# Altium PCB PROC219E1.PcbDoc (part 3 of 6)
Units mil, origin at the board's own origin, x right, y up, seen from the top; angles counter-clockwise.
Board outline 5354.33 x 5354.33 mil, 4 copper layers (Top Layer, Inner Layer 1, Inner Layer 2, Bottom Layer), stack 62.449 mil thick; 579 components, 299 nets, 1709 pads, 802 vias.
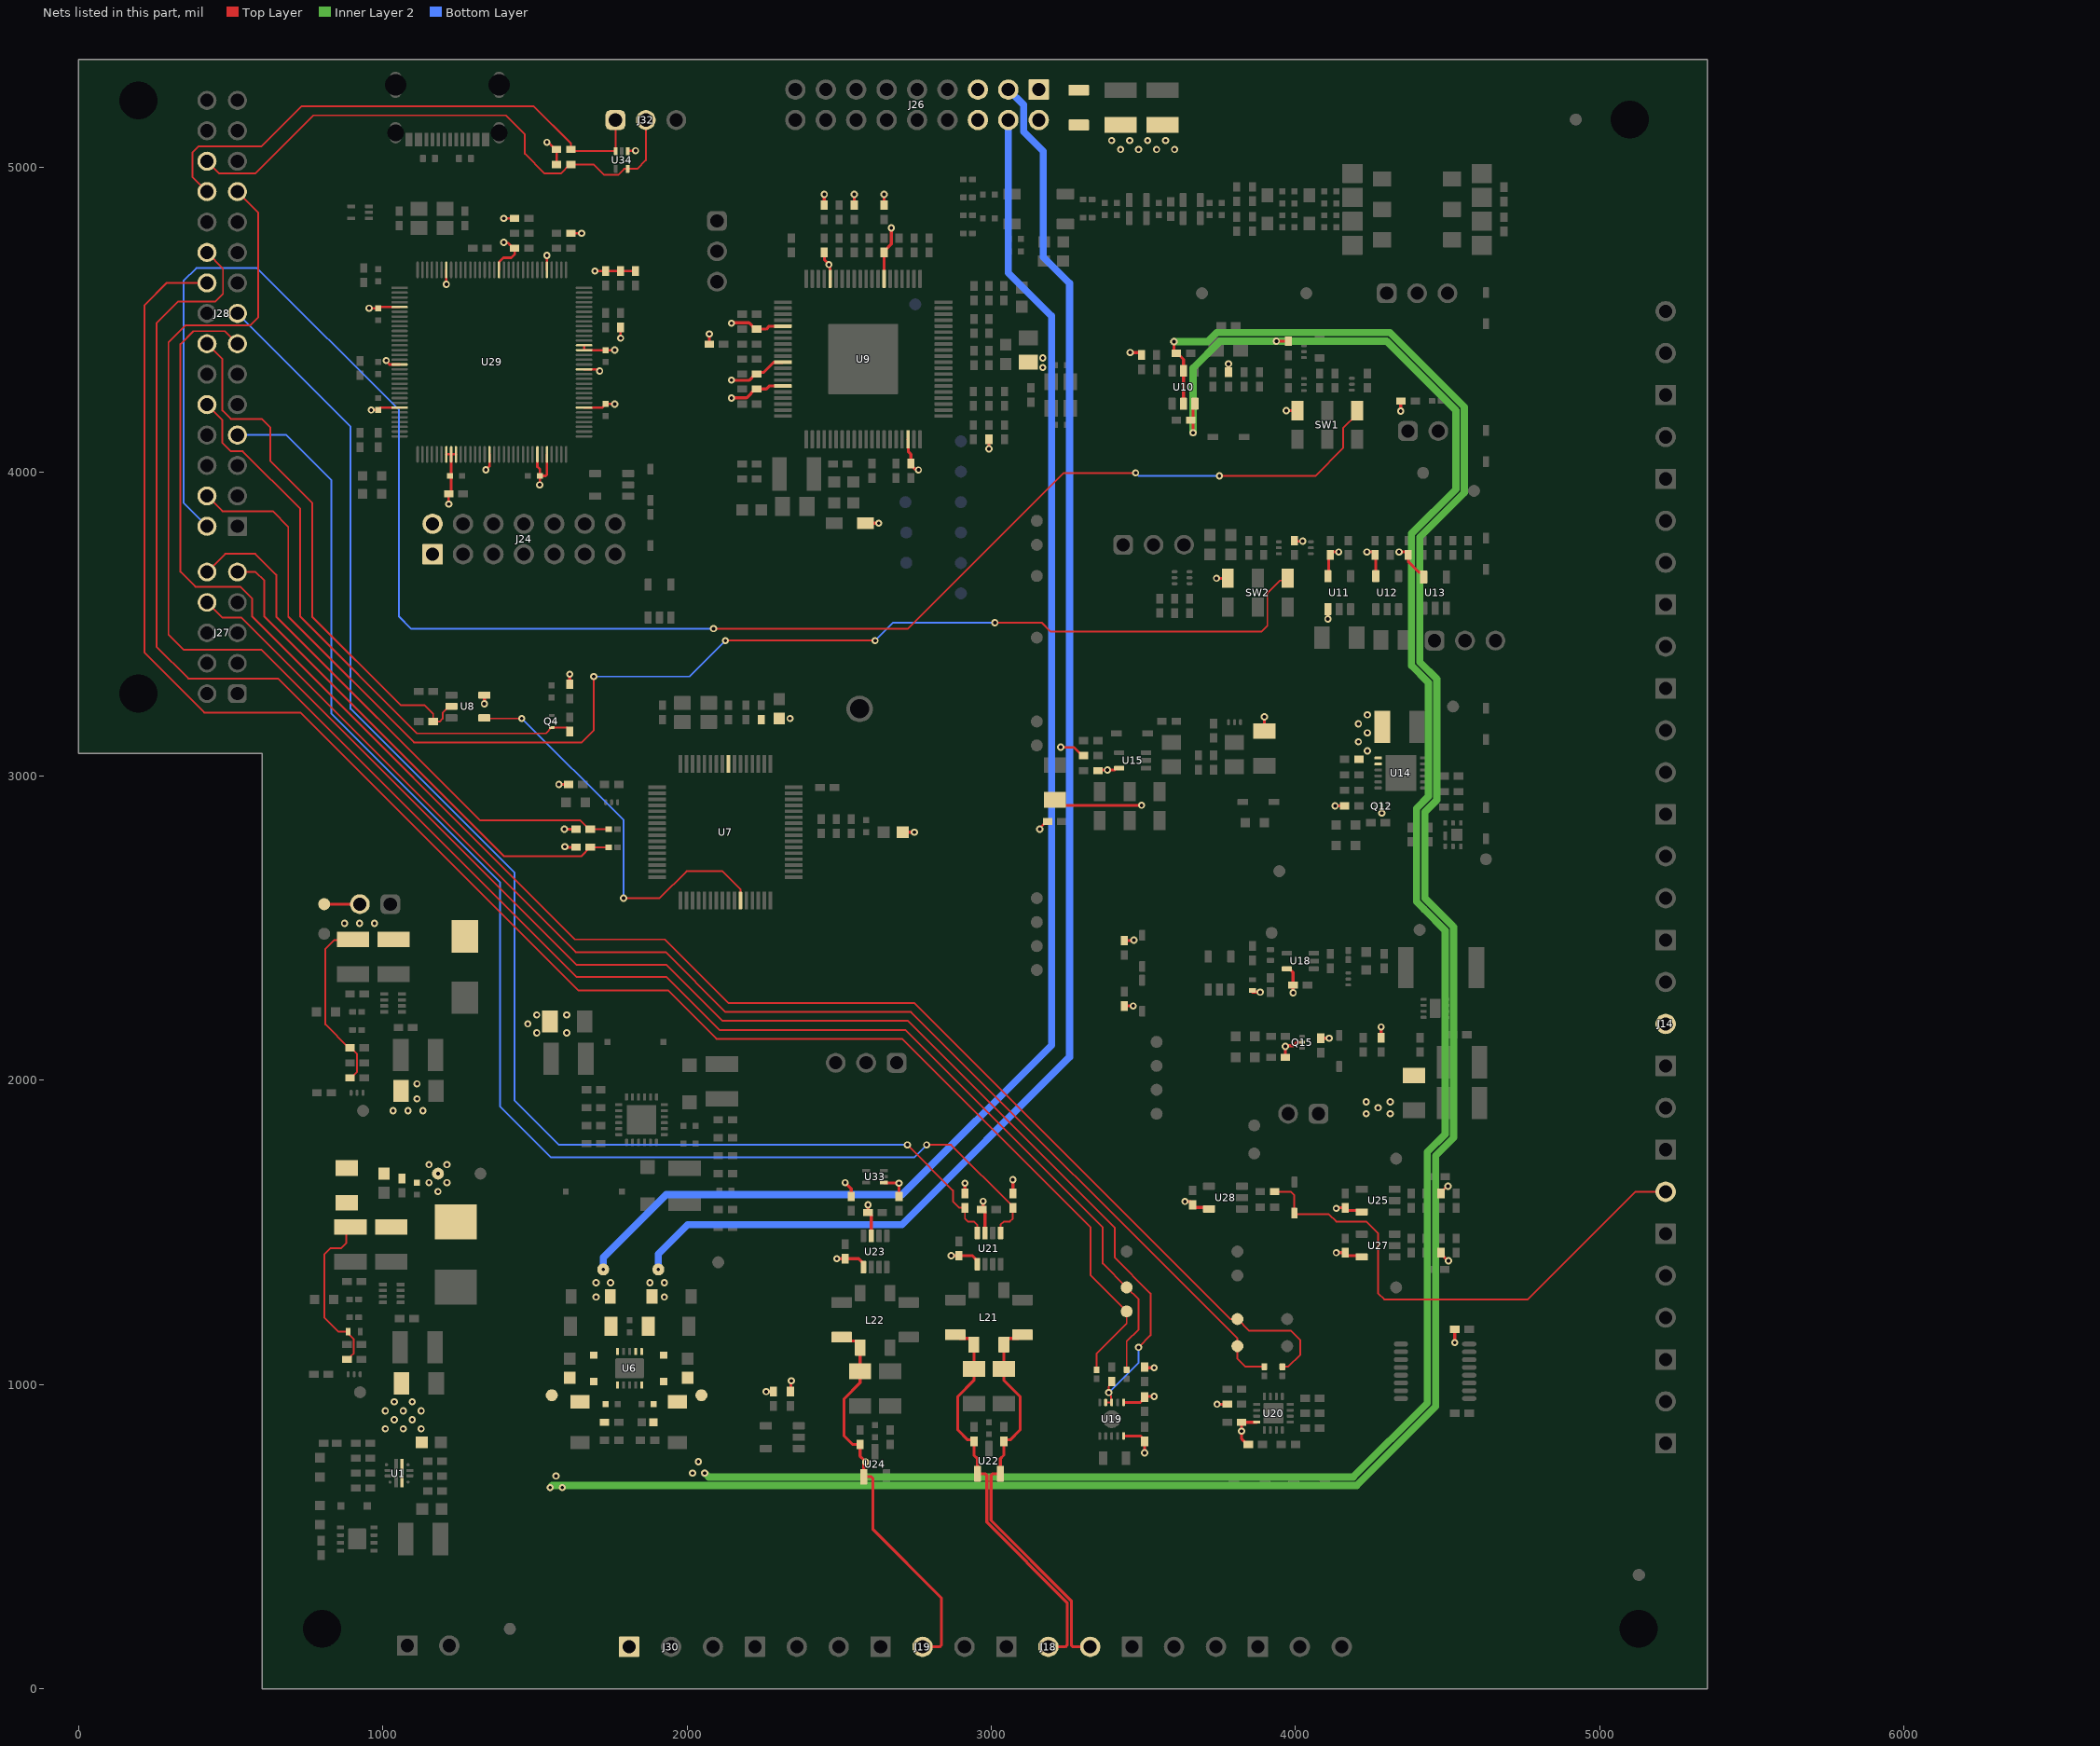
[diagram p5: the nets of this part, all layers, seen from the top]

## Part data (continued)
L13: library part CMP-0100963-1, "WE-PMCI SMT Power Molded Chip Inductor, size 1210, 2.2uH, 4.5A, 75mOhm", DC Resistance=70mOhm, DC Resistance Max=75mOhm, Manufacturer="Wurth Elektronik", Operating Temperature Max=125°C, Operating Temperature Min=-40°C, Rated Current=4.5A, Saturation Current=4.8A, Self Resonant Frequency=35MHz
L15 L16 L19 L20: library part CMP-0124834-1, "Wire Wound RF Inductor 270nH ±2% 260mA 2.42Ω 0603 (1608)", Manufacturer=Murata, Operating Temperature Range="-55°C to +125°C", Self Resonant Frequency=1.25GHz, Test Frequency=100MHz, Tolerance_%=2%
L17 L18: library part CMP-0124833-1, "Multilayer Type Inductor for Power Lines, 0805 (2012), 4.7μH, 20%, 0.288Ω, 0.8A", Manufacturer=Murata, Operating Temperature Range="-55℃ to +125℃", Self Resonant Frequency=30MHz, Test Frequency=1MHz, Tolerance_%=20%
L21 L22: library part CMP-0084086-1, "100µH @ 100kHz 2 Line Common Mode Choke Surface Mount 5.8 kOhms @ 10MHz 150mA DCR 2Ohm", Digikey Part Number=445-3959-1-ND, Impedance At Frequency="5800Ω @ 10MHz", Manufacturer=TDK, Mouser Part Number=810-ACT45B1012PTL003, Operating Temperature Range="-40°C to +150°C", Test Frequency=100kHz, Tolerance_%=+50/-30%
Logo1: library part CMP-0074844-1
Logo2 Logo6: library part CMP-0074838-1, "Texas Instrument Corporate Signature"
Logo3: library part CMP-0074840-1, "ESD Susceptible Symbol"
Logo4: library part CMP-0074847-1, "FCC_disclaimer"
Logo5: library part CMP-0074769-4, Manufacturer="Texas Instruments"
MH1 MH2 MH3 MH4 MH5: library part CMP-0078424-2, "PCB Mounting Hole, No Pad", Manufacturer=Any, PartNumber=N/A
NT1: library part CMP-0078142-6, "Single point connection between nets.", Manufacturer=N/A
Q1 Q2 Q3 Q4 Q6 Q7 Q9 Q10 Q11 Q14 Q16: library part CMP-0067551-1, "MOSFET, N-CH, 30 V, 5.9 A, YJK0003A (PICOSTAR-3)", Alternate Manufacturer=None, Manufacturer="Texas Instruments", Supplier Part Number 1=296-45068-1-ND, Value1="0.033 ohm", Value2="1.9 nC"
Q5 Q8 Q12 Q15: library part CMP-0000031-3, "MOSFET, P-CH, -20 V, -5.3 A, YJK0003A (PICOSTAR-3)", Alternate Manufacturer=None, Manufacturer="Texas Instruments", Value2="2.7 nC"
Q13: library part CMP-0000585-1, "MOSFET, N-CH, 30 V, 22 A, DQK0006C (WSON-6)", Alternate Manufacturer=None, Manufacturer="Texas Instruments", Supplier Part Number 1=296-37193-1-ND, Value1=0.02, Value2="2.4 nC"
R1 R7 R13 R19 R42 R43 R44 R45 R47 R48 R49 R50 R96 R123 R127 R134 R135 R140 R141 R148 R167 R168 R169 R170: library part CMP-0026700-1, "RES, 4.70 k, 1%, 0.1 W, 0402", Manufacturer=Panasonic, Power_W=100mW, Supplier Part Number 1=P4.70KLCT-ND, TempCo="100 ppm/C", Tolerance_%=1%, Value2=0.1W, Value_Code=4k70, ValueDisplayed=4.70k
R2: library part CMP-0026393-2, "RES, 475 k, 1%, 0.063 W, AEC-Q200 Grade 0, 0402", Manufacturer=Vishay-Dale, Power_W=63mW, Supplier Part Number 1=541-475KLCT-ND, TempCo="100 ppm/C", Tolerance_%=1%, Value2=0.063W, Value_Code=475k
R3 R133 R138 R139 R144: library part CMP-0094724-1, "Jumper 0.25W, 1/4W Chip Resistor 1206 (3216 Metric) - Thick Film", Digikey Part Number=541-4170-1-ND, Manufacturer=Vishay, Mouser Part Number=71-CRCW12060000Z0EAC, Operating Temperature Range="-55°C to +155°C", Power_W=250mW
R4: library part CMP-0025975-3, "RES, 11.0 k, 1%, 0.063 W, AEC-Q200 Grade 0, 0402", Manufacturer=Vishay-Dale, Power_W=63mW, Supplier Part Number 1=541-11.0KLCT-ND, TempCo="100 ppm/C", Tolerance_%=1%, Value2=0.063W, Value_Code=11k0, ValueDisplayed=11.0k
R5: library part CMP-0026542-2, "RES, 750, 1%, 0.063 W, AEC-Q200 Grade 0, 0402", Manufacturer=Vishay-Dale, Power_W=63mW, Supplier Part Number 1=541-750LCT-ND, TempCo="100 ppm/C", Tolerance_%=1%, Value2=0.063W, Value_Code=750R, ValueDisplayed=750
R6 R37: library part CMP-0026737-1, "RES, 47.0 k, 1%, 0.0625 W, 0402", Manufacturer="Yageo America", Power_W=62.5mW, Supplier Part Number 1=311-47.0KLRCT-ND, TempCo="100 ppm/C", Tolerance_%=1%, Value2=0.0625W, Value_Code=47k0, ValueDisplayed=47.0k
R8 R11 R14 R17 R33 R34 R51 R52 R53 R54 R55 R56 R67 R118 R125 R126 R128 R131: library part CMP-0095664-1, "Jumper 0.063W, 1/16W Chip Resistor 0402 (1005 Metric) - Thick Film", Digikey Part Number=A106025CT-ND, Manufacturer="TE Connectivity", Mouser Part Number=279-CRG0402ZR, Operating Temperature Range="-55°C to +155°C", Power_W=62.5mW, TempCo=200ppm/°C
R9 R12 R15 R18 R23 R27 R29 R31 R32 R36 R38 R39 R40 R70 R71 R72 R75 R76 R78 R82 R85 R86 R87 R88 R90 R91 R92 R93 R95 R99 R101 R103 R110 R111 R112 R129 R130 R132 R145 R146 R147 R149 R150 R151 R161 R162: library part CMP-0026658-1, "RES, 10.0 k, 1%, 0.1 W, 0402", Manufacturer=Panasonic, Power_W=100mW, Supplier Part Number 1=P10.0KLCT-ND, TempCo="100 ppm/C", Tolerance_%=1%, Value2=0.1W, Value_Code=10k0, ValueDisplayed=10.0k
R10: library part CMP-0026539-2, "RES, 73.2 k, 1%, 0.063 W, AEC-Q200 Grade 0, 0402", Manufacturer=Vishay-Dale, Power_W=63mW, Supplier Part Number 1=541-73.2KLCT-ND, TempCo="100 ppm/C", Tolerance_%=1%, Value2=0.063W, Value_Code=73k2, ValueDisplayed=73.2k
R16: library part CMP-0077552-1, "RES, 45.3 k, 1%, 0.063 W, 0402", Manufacturer="Yageo America", Power_W=63mW, Supplier Part Number 1=311-45.3KLRCT-ND, TempCo="100 ppm/C", Tolerance_%=1%, Value2=0.063W, Value_Code=45k3, ValueDisplayed=45.3k
R20: library part CMP-0123016-1, "Res Thick Film 0402 91K Ohm 1% 0.063W(1/16W) ±100ppm/C Pad SMD T/R", Digikey Part Number=13-RC0402FR-1391KLCT-ND, Manufacturer=YAGEO, Mouser Part Number=603-RC0402FR-1391KL, Operating Temperature Range="-55°C to +155°C", Power_W=63mW, TempCo=100ppm/°C, Tolerance_%=1%
R21: library part CMP-0026615-3, "RES, 976 k, 1%, 0.063 W, AEC-Q200 Grade 0, 0402", Manufacturer=Vishay-Dale, Power_W=63mW, Supplier Part Number 1=541-976KLCT-ND, TempCo="100 ppm/C", Tolerance_%=1%, Value2=0.063W, Value_Code=976k
R22: library part CMP-0026609-3, "RES, 93.1 k, 1%, 0.063 W, AEC-Q200 Grade 0, 0402", Manufacturer=Vishay-Dale, Power_W=63mW, Supplier Part Number 1=541-93.1KLCT-ND, TempCo="100 ppm/C", Tolerance_%=1%, Value2=0.063W, Value_Code=93k1, ValueDisplayed=93.1k
R24: library part CMP-0120089-1, "68 kOhms ±1% 0.063W, 1/16W Chip Resistor 0402 (1005 Metric) Thick Film", Digikey Part Number=1292-WR04X6802FTLCT-ND, Manufacturer="Walsin Technology", Mouser Part Number=791-WR04X6802FTL, Operating Temperature Range="-55°C to +155°C", Power_W=63mW, TempCo=100ppm/°C, Tolerance_%=1%
R25: library part CMP-0026549-2, "RES, 787 k, 1%, 0.063 W, AEC-Q200 Grade 0, 0402", Manufacturer=Vishay-Dale, Power_W=63mW, Supplier Part Number 1=541-787KLCT-ND, TempCo="100 ppm/C", Tolerance_%=1%, Value2=0.063W, Value_Code=787k
R26 R58 R158: library part CMP-0026656-1, "RES, 100, 1%, 0.1 W, 0402", Manufacturer=Panasonic, Power_W=100mW, Supplier Part Number 1=P100LCT-ND, TempCo="100 ppm/C", Tolerance_%=1%, Value2=0.1W, Value_Code=100R, ValueDisplayed=100
R28 R30 R84 R102: library part CMP-0026721-1, "RES, 100 k, 1%, 0.0625 W, 0402", Manufacturer="Yageo America", Power_W=62.5mW, Supplier Part Number 1=311-100KLRCT-ND, TempCo="100 ppm/C", Tolerance_%=1%, Value2=0.0625W, Value_Code=100k
R35 R94 R107 R109 R120: library part CMP-0026878-3, "RES, 220, 5%, 0.063 W, AEC-Q200 Grade 0, 0402", Manufacturer=Vishay-Dale, Power_W=63mW, Supplier Part Number 1=541-220JCT-ND, TempCo="200 ppm/C", Tolerance_%=5%, Value2=0.063W, Value_Code=220R, ValueDisplayed=220
R41 R46: library part CMP-0022751-4, "RES, 10.0, 1%, 0.1 W, 0603", Manufacturer=Yageo, Power_W=100mW, Supplier Part Number 1=311-10.0HRCT-ND, TempCo="100 ppm/C", Tolerance_%=1%, Value2=0.1W, Value_Code=10R0, ValueDisplayed=10.0
R57 R77 R119: library part CMP-0026727-1, "RES, 1.00 M, 1%, 0.063 W, 0402", Manufacturer="Yageo America", Power_W=63mW, Supplier Part Number 1=311-1.00MLRCT-ND, TempCo="100 ppm/C", Tolerance_%=1%, Value2=0.063W, Value_Code=1M00, ValueDisplayed=1.00M
R59: library part CMP-0026468-2, "RES, 5.76 k, 1%, 0.063 W, AEC-Q200 Grade 0, 0402", Manufacturer=Vishay-Dale, Power_W=63mW, Supplier Part Number 1=541-5.76KLCT-ND, TempCo="100 ppm/C", Tolerance_%=1%, Value2=0.063W, Value_Code=5k76, ValueDisplayed=5.76k
R60 R62 R63: library part CMP-0026677-1, "RES, 200 k, 1%, 0.1 W, 0402", Manufacturer=Panasonic, Power_W=100mW, Supplier Part Number 1=P200KLCT-ND, TempCo="100 ppm/C", Tolerance_%=1%, Value2=0.1W, Value_Code=200k
R61: library part CMP-0019089-2, "RES, 1.00 k, 0.1%, 0.25 W, 0805", Manufacturer="TE Connectivity", Power_W=250mW, Supplier Part Number 1=A110543CT-ND, TempCo="25 ppm/C", Tolerance_%=0.1%, Value2=0.25W, Value_Code=1k00, ValueDisplayed=1.00k
R64 R106: library part CMP-0026449-2, "RES, 54.9 k, 1%, 0.063 W, AEC-Q200 Grade 0, 0402", Manufacturer=Vishay-Dale, Power_W=63mW, Supplier Part Number 1=541-54.9KLCT-ND, TempCo="100 ppm/C", Tolerance_%=1%, Value2=0.063W, Value_Code=54k9, ValueDisplayed=54.9k
R65: library part CMP-0026494-2, "RES, 63.4 k, 1%, 0.063 W, AEC-Q200 Grade 0, 0402", Manufacturer=Vishay-Dale, Power_W=63mW, Supplier Part Number 1=541-63.4KLCT-ND, TempCo="100 ppm/C", Tolerance_%=1%, Value2=0.063W, Value_Code=63k4, ValueDisplayed=63.4k
R66 R83 R108 R117 R154 R155 R156 R157: library part CMP-0026725-1, "RES, 1.00 k, 1%, 0.0625 W, 0402", Manufacturer="Yageo America", Power_W=62.5mW, Supplier Part Number 1=311-1.00KLRCT-ND, TempCo="100 ppm/C", Tolerance_%=1%, Value2=0.0625W, Value_Code=1k00, ValueDisplayed=1.00k
R68: library part CMP-0026241-2, "RES, 2.74 k, 1%, 0.063 W, AEC-Q200 Grade 0, 0402", Manufacturer=Vishay-Dale, Power_W=63mW, Supplier Part Number 1=541-2.74KLCT-ND, TempCo="100 ppm/C", Tolerance_%=1%, Value2=0.063W, Value_Code=2k74, ValueDisplayed=2.74k
R69: library part CMP-0026082-3, "RES, 1.30 k, 1%, 0.063 W, AEC-Q200 Grade 0, 0402", Manufacturer=Vishay-Dale, Power_W=63mW, Supplier Part Number 1=541-1.30KLCT-ND, TempCo="100 ppm/C", Tolerance_%=1%, Value2=0.063W, Value_Code=1k30, ValueDisplayed=1.30k
R73 R97 R104: library part CMP-0018797-2, "RES, 1.00 k, 0.1%, 0.25 W, 1206", Manufacturer="TE Connectivity", Power_W=250mW, Supplier Part Number 1=A105676-ND, TempCo="15 ppm/C", Tolerance_%=0.1%, Value2=0.25W, Value_Code=1k00, ValueDisplayed=1.00k
R74: library part CMP-0019464-2, "RES, 10.0 k, 0.1%, 0.125 W, 0805", Manufacturer="Yageo America", Power_W=125mW, Supplier Part Number 1=603-RT0805BRD0710KL, TempCo="25 ppm/C", Tolerance_%=0.1%, Value2=0.125W, Value_Code=10k0, ValueDisplayed=10.0k
R79 R100: library part CMP-0026919-5, "RES, 3.6 k, 5%, 0.063 W, AEC-Q200 Grade 0, 0402", Manufacturer=Vishay-Dale, Power_W=63mW, Supplier Part Number 1=541-3.6KJCT-ND, TempCo="200 ppm/C", Tolerance_%=5%, Value2=0.063W, Value_Code=3k60, ValueDisplayed=3.6k
R80: library part CMP-0024081-3, "RES, 2.74 k, 0.1%, 0.1 W, 0603", Manufacturer="Yageo America", Power_W=100mW, TempCo="25 ppm/C", Tolerance_%=0.1%, Value2=0.1W, Value_Code=2k74, ValueDisplayed=2.74k
R81: library part CMP-0023888-3, "RES, 1.30 k, 0.1%, 0.1 W, 0603", Manufacturer="Yageo America", Power_W=100mW, TempCo="25 ppm/C", Tolerance_%=0.1%, Value2=0.1W, Value_Code=1k30, ValueDisplayed=1.30k
R89: library part CMP-0026017-3, "RES, 14.7 k, 1%, 0.063 W, AEC-Q200 Grade 0, 0402", Manufacturer=Vishay-Dale, Power_W=63mW, Supplier Part Number 1=541-14.7KLCT-ND, TempCo="100 ppm/C", Tolerance_%=1%, Value2=0.063W, Value_Code=14k7, ValueDisplayed=14.7k
R98 R105: library part CMP-0019763-2, "RES, 200, 0.1%, 0.125 W, 0805", Manufacturer="Yageo America", Power_W=125mW, TempCo="25 ppm/C", Tolerance_%=0.1%, Value2=0.125W, Value_Code=200R, ValueDisplayed=200
R113 R115: library part CMP-0001694-1, "150 Ohms ±0.1% 0.063W, 1/16W Chip Resistor 0402 (1005 Metric) Anti-Sulfur, Automotive AEC-Q200, Moisture Resistant Thin Film", Digikey Part Number=541-2077-1-ND, Manufacturer="Vishay Dale", Mouser Part Number=71-TNPW0402150RBEED, Operating Temperature Range="-55°C to +155°C", Power_W=100mW, TempCo=25ppm/°C, Tolerance_%=0.1%
R114: library part CMP-0026201-2, "RES, 25.5 k, 1%, 0.063 W, AEC-Q200 Grade 0, 0402", Manufacturer=Vishay-Dale, Power_W=63mW, Supplier Part Number 1=541-25.5KLCT-ND, TempCo="100 ppm/C", Tolerance_%=1%, Value2=0.063W, Value_Code=25k5, ValueDisplayed=25.5k
R116: library part CMP-0015788-2, "RES, 0.5, 1%, 2 W, 2512", Manufacturer="Stackpole Electronics Inc", Power_W=2W, Supplier Part Number 1=CSRN2512FKR500CT-ND, TempCo="200 ppm/C", Tolerance_%=1%, Value_Code=R500, ValueDisplayed=0.5
R121 R122 R152: library part CMP-0065360-1, "RES, 10.0 k, .1%, .0625 W, 0402", Manufacturer="Yageo America", Power_W=62.5mW, Supplier Part Number 1=YAG1346CT-ND, TempCo="25 ppm/C", Tolerance_%=0.1%, Value1=.1%, Value2=.0625W, Value_Code=10k0, ValueDisplayed=10.0k
R124: library part CMP-0126832-1, "Res Thick Film 0805 120 Ohm 1% 0.5W(1/2W) ±100ppm/C Pad SMD T/R Automotive", Digikey Part Number=846-SDR10EZPF1200CT-ND, Manufacturer=Rohm, Mouser Part Number=755-SDR10EZPF1200, Operating Temperature Range="-55°C to +155°C", Power_W=660mW, TempCo=100ppm/°C, Tolerance_%=1%
R136 R137 R142 R143: library part CMP-0017077-3, "RES, 59.0, 1%, 0.25 W, AEC-Q200 Grade 0, 1206", Manufacturer=Vishay-Dale, Power_W=250mW, Supplier Part Number 1=541-59.0FCT-ND, TempCo="100 ppm/C", Tolerance_%=1%, Value2=0.25W, Value_Code=59R0, ValueDisplayed=59.0
R153: library part CMP-0026333-2, "RES, 3.32 k, 1%, 0.063 W, AEC-Q200 Grade 0, 0402", Manufacturer=Vishay-Dale, Power_W=63mW, Supplier Part Number 1=541-3.32KLCT-ND, TempCo="100 ppm/C", Tolerance_%=1%, Value2=0.063W, Value_Code=3k32, ValueDisplayed=3.32k
R159 R160: library part CMP-0026736-1, "RES, 470, 1%, 0.063 W, 0402", Manufacturer="Yageo America", Power_W=63mW, Supplier Part Number 1=311-470LRCT-ND, TempCo="100 ppm/C", Tolerance_%=1%, Value2=0.063W, Value_Code=470R, ValueDisplayed=470
R163: library part CMP-0026413-2, "RES, 4.87 k, 1%, 0.063 W, AEC-Q200 Grade 0, 0402", Manufacturer=Vishay-Dale, Power_W=63mW, Supplier Part Number 1=541-4.87KLCT-ND, TempCo="100 ppm/C", Tolerance_%=1%, Value2=0.063W, Value_Code=4k87, ValueDisplayed=4.87k
R164: library part CMP-0026946-3, "RES, 51, 5%, 0.063 W, AEC-Q200 Grade 0, 0402", Manufacturer=Vishay-Dale, Power_W=63mW, Supplier Part Number 1=541-51JCT-ND, TempCo="200 ppm/C", Tolerance_%=5%, Value2=0.063W, Value_Code=51R0, ValueDisplayed=51
R165 R166: library part CMP-0093159-1, "5.1kΩ ±1% 0.063W 0402 Thick Film Chip Resistor AEC-Q200 compliant", Manufacturer="Stackpole Electronics", Operating Temperature Range="-55°C to +155°C", Power_W=63mW, TempCo=100ppm/°C, Tolerance_%=1%
SH-J1 SH-J2 SH-J3 SH-J4 SH-J5 SH-J6 SH-J7 SH-J8 SH-J9 SH-J10 SH-J11 SH-J12: library part CMP-0003761-2, "Shunt, 2.54mm, Gold, Black", Manufacturer="Wurth Elektronik", Supplier Part Number 1=732-2678-ND
SW1 SW2 SW3: library part CMP-10038-000009-1, "SWITCH SLIDE DPDT 300MA 6V", Current Rating=300mA, Manufacturer=C&K, Max Operating Temperature=85°C, Min Operating Temperature=-40°C, Voltage Rating (DC)=6V
T1: library part CMP-0124838-1, "Wideband RF transformer, 1:1, 0.0035-125 MHz, SMT, RoHS", Frequency_Fixed=125MHz, Manufacturer=Coilcraft, Mouser Part Number=994-PWB3010LC, Operating Temperature Range=to, Voltage_Isolation_Vrms=300Vrms
T2: library part CMP-0124847-1, "215µH Isolation and Data Interface (Encapsulated) Pulse Transformer 1:1 Surface Mount", Digikey Part Number=2457-ZA9756-AED-ND, Manufacturer=Coilcraft, Operating Temperature Range=to, Voltage_Isolation_Vrms=3000Vrms
TP1 TP2 TP3 TP4 TP5 TP6 TP7 TP8 TP9 TP10 TP11 TP12 TP13 TP14 TP15 TP16 TP17 TP18 TP19 TP20 TP21 TP22 TP23 TP24 TP25 TP26 TP27 TP28 TP29 TP30 TP31 TP32 TP33 TP34 TP35 TP36 TP37 TP38 TP39 TP40 TP41 TP42 TP43 TP44 TP45 TP46 TP47 TP48 TP49 TP50 TP51 TP52 TP53 TP54 TP55 TP56 TP57: library part CMP-0003825-1, "1mm Test Point, SMT", Manufacturer=Any
TP58: library part CMP-0055148-2, "Test Point, Multipurpose, Black, TH", Color=Black, Manufacturer="Keystone Electronics", Supplier Part Number 1=36-5011-ND
U1: library part CMP-0091660-1, "2.7 - 23 V, 5.5 A, 28 mΩ True Reverse Current Blocking eFuse with Input Reverse Polarity Protection", Manufacturer="Texas Instruments", Max Supply Voltage=23V, Min Supply Voltage=2.7V, Nominal Supply Current=428uA, Operating Temperature Range="-40°C to +125°C", Output Voltage=2.7-23V
U2: library part CMP-0083940-3, "14 V Bidirectional Flat-Clamp Surge Protection Device, DRB0008A (VSON-8)", Alternate Manufacturer="Texas Instruments", Alternate PartNumber=TVS1401DRBT, Operating Temperature Range="-40 to 125 C"
U3 U4: library part CMP-0861058-2, "4.2-V to 17-V Input, 3-A Synchronous Buck Converter, DRL0008A (SOT-5X3-8)", Alternate Manufacturer="Texas Instruments"
U5: library part CMP-0034952-2, "Postive and Negative Output DC-DC Converter, 2.7 to 5.5 V, -40 to 85 degC, 24-pin QFN (RGE24), Green (RoHS & no Sb/Br)", Manufacturer="Texas Instruments", Rating=Catalog, Switching Frequency(Typ)(kHz)=1400
U6: library part CMP-0013435-7, "Dual, 150mA, Wide-Vin, Positive and Negative Low-Dropout (LDO) Voltage Regulator, DSC0010J (WSON-10)", Alternate Manufacturer="Texas Instruments", Alternate PartNumber=TPS7A3901DSCT, Operating Temperature Range="-40 to 125 C", Rating=Catalog
U7: library part CMP-0093960-1, "Mixed-Signal Microcontrollers With CAN-FD Interface LQFP64", Frequency_Fixed=80MHz, Manufacturer="Texas Instruments", Max Supply Voltage=3.6V, Min Supply Voltage=1.62V, Operating Temperature Range="-40°C to +125°C"
U8: library part CMP-0051300-2, "Single Bus Buffer Gate With 3-State Outputs, DBV0005A, LARGE T&R", Alternate Manufacturer="Texas Instruments", F @ Nom Voltage(Max)(Mhz)=150, Generic Part Number=SN74LVC1G125, ICC @ Nom Voltage(Max)(mA)=0.01, Operating Temperature Range(C)="-40 to 125,-40 to 85", Rating=Catalog, tpd @ Nom Voltage(Max)(ns)=9,5.5,4.5,4, Voltage(Nom)(V)=1.8,2.5,3.3,5
U9: library part CMP-0124871-1, Manufacturer="Lumissil Microsystems", Operating Temperature Range=to
U10: library part CMP-0080757-2, "40 V, microPower, Push-Pull Comparator with Shutdown, DBV0006A (SOT-23-6)", Alternate Manufacturer="Texas Instruments"
U11 U12: library part CMP-0067409-1, "Low-Voltage, Low On-State Resistance SPST CMOS Analog Switches, DBV0005A (SOT-23-5)", Alternate Manufacturer="Texas Instruments"
U13: library part CMP-0092482-1, "Single 4.5-MHz, 16-V rail-to-rail input/output, low-offset voltage, low-noise op amp 5-SOT-23 -40 to 125", Digikey Part Number=296-TLV9151IDBVRCT-ND, Input Bias Current=0.00001uA, Input Offset Voltage=0.125mV, Manufacturer="Texas Instruments", Max Dual Supply Voltage=8V, Max Supply Voltage=16V, Min Dual Supply Voltage=1.35V, Min Supply Voltage=2.7V, Mouser Part Number=595-TLV9151IDBVR, Nominal Supply Current=560uA, Operating Temperature Range="-40°C to +125°C", Output Current Per Channel=75mA, Voltage Gain=120dB
U14: library part CMP-0120107-1, "60-V, 100-mΩ, Single-Channel Smart High-Side Switch", Manufacturer="Texas Instruments", Max Supply Voltage=60V, Min Supply Voltage=6V, Nominal Supply Current=0.98-1mA, Operating Temperature Range="-40°C to +125°C", Part Number=TPS281C100DNTR
U15 U18: library part CMP-0860894-1, "Low power, small size comparator with push-pull output, DCK0005A (SOT-SC70-5)", Alternate Manufacturer="Texas Instruments", Alternate PartNumber=TLV7011DCKT, Operating Temperature Range="-40 to 125 C", Rating=Catalog
U16: library part CMP-0090279-2, "1.6A H-bridge motor driver, PWM, PH/EN, ½ bridge control, with low power sleep mode", Manufacturer="Texas Instruments", Max Supply Voltage=18V, Min Supply Voltage=4.5V, Operating Temperature Range="-40°C to +150°C", Part Number=DRV8220DSG, Switching Frequency=100kHz
U17: library part CMP-0032940-1, "Adjustable Precision Shunt Regulator, 34 ppm / degC, 100 mA, -40 to 125 degC, 5-pin SOT-23 (DBV), Green (RoHS & no Sb/Br)", Manufacturer="Texas Instruments", Rating=Catalog, Temp Coeff(Max)(ppm/ degree C)=92, Temp Coeff(Typ)(ppm/ degree C)=34
U19: library part CMP-0094911-1, "3-V to 5.5-V Small RS-485 Transceivers With Integrated 4-kV Surge Protection and High Bus-Fault Protection in Small Packages", Manufacturer="Texas Instruments", Max Supply Voltage=5.5V, Min Supply Voltage=1.65V, Operating Temperature Range="-40°C to +150°C"
U20: library part CMP-0123242-1, "3- to 5.5-V single channel 1Mbps RS-232 line driver/receiver with +/-15-kV IEC-ESD protection", Digikey Part Number=296-TRSF3221EIRGTRCT-ND, Manufacturer="Texas Instruments", Max Supply Voltage=5.5V, Min Supply Voltage=3V, Mouser Part Number=595-TRSF3221EIRGTR, Nominal Supply Current=0.3mA, Operating Temperature Range="-40°C to +85°C"
U21 U23: library part CMP-0122870-1, "Enhanced automotive CAN transceiver with standby and 1.8-V I/O support 8-SOT-23-THIN -40 to 150", Digikey Part Number=296-TCAN1044AVDDFRQ1CT-ND, Manufacturer="Texas Instruments", Max Supply Voltage=5.5V, Min Supply Voltage=1.7V, Mouser Part Number=595-TCAN1044AVDDFRQ1, Operating Temperature Range="-40°C to +150°C"
U22 U24: library part CMP-0093261-1, "24-V, 2-Channel ESD Protection Diode for In-Vehicle Networks", Breakdown Voltage=25.5V, Clamping Voltage=32V, Manufacturer="Texas Instruments", Operating Temperature Range="-55°C to +150°C", ValueDisplayed=3pF
U25 U27: library part CMP-0051702-2, "Single Schmitt-Trigger Buffer, DBV0005A, LARGE T&R", F @ Nom Voltage(Max)(Mhz)=150, Generic Part Number=SN74LVC1G17, ICC @ Nom Voltage(Max)(mA)=0.01, Manufacturer="Texas Instruments", Operating Temperature Range(C)="-40 to 125,-40 to 85", Rating=Catalog, tpd @ Nom Voltage(Max)(ns)=11,6.5,5.5,5, Voltage(Nom)(V)=1.8,2.5,3.3,5
U26: library part CMP-0033666-1, "7-Channel Low Side Driver, 0 to 40 V VOUT, -40 to 125 degC, 16-Pin TSSOP (PW), RoHS, Tape and Reel", PartNumber=TPL7407LA, Temperature Max="125 degC", Temperature Min="-40 degC"
U28: library part CMP-0081549-1, "Low-Power, Rail-to-Rail In and Out, 1-MHz Operational Amplifier, DBV0005A (SOT-23-5)", Alternate Manufacturer="Texas Instruments"
U29: library part CMP-0077953-1, "MSP432E401YTPDT, PDT0128A (TQFP-128)", Alternate Manufacturer="Texas Instruments", Alternate PartNumber=MSP432E401YTPDTR
U30 U31 U35: library part CMP-0085635-1, "Data-Line Surge and ESD Protection Diode Array, DBV0005A (SOT-23-5)", Alternate Manufacturer="Texas Instruments", Operating Temperature Range="-40 to 125 C", Rating=Catalog
U32 U33 U34: library part CMP-0043096-2, "Low-Capacitance + / - 15 kV ESD-Protection Array for High-Speed Data Interfaces, 2 Channels, -40 to +85 degC, 5-pin SOT (DRL), Green (RoHS & no Sb/Br)", Breakdown Voltage(Min)(V)=11, IO Capacitance(Typ)(pF)=1.5, IO Leakage Current(nA)=1, Manufacturer="Texas Instruments"
Y1: library part CMP-0124814-1, "32 MHz ±10ppm Crystal 9pF 40 Ohms 4-SMD, No Lead", Digikey Part Number=1923-830103622909CT-ND, Frequency Stability=15ppm, Frequency Tolerance=10ppm, Frequency_Fixed=32MHz, Load Capacitance=9pF, Manufacturer="Wurth Electronics", Mouser Part Number=710-830103622909, Operating Temperature Range="-40°C to +85°C"
Y2: library part CMP-0124828-1, "Crystal 25MHz ±10ppm (Tol) ±20ppm (Stability) 8pF FUND 100Ohm 4-Pin SMD T/R", Digikey Part Number=535-14059-1-ND, Frequency Stability=20ppm, Frequency Tolerance=10ppm, Frequency_Fixed=25MHz, Load Capacitance=8pF, Manufacturer=Abracon, Mouser Part Number=815-8W25-8D1XT, Operating Temperature Range="-40°C to +85°C"
Y3: library part CMP-0004635-3, "Crystal, 16 MHz, 8pF, SMD", Frequency Stability=+/-30ppm, Frequency_Fixed=16MHz, Manufacturer=NDK, Supplier Part Number 1=644-1157-1-ND
ZZ2: library part CMP-0077236-1
ZZ3: library part CMP-0077237-1
ZZ4: library part CMP-0077238-1

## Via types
v1: diameter 23.62, hole 11.81, Top Layer to Bottom Layer, tented both sides, 802 vias

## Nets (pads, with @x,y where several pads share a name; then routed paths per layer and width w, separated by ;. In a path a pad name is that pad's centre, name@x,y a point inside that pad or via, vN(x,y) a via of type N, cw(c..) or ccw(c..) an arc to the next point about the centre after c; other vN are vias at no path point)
3.3V: C18.1 C19.1 C20.1 C40.1 C41.1 C79.1 C80.1 C81.1 C82.1 C83.1 C84.1 C120.1 C124.2 C127.1 C128.1 C129.1 C134.1 C139.1 C147.1 C148.1 C149.1 C151.2 C152.2 C153.2 C154.2 C155.2 C156.1 C157.1 C158.2 FB1.2 J24.1 J24.2 J26.6 L4.2 L9.1 L11.2 Q12.2@4283.46,2901.57 Q15.2@4021.85,2124.78 R31.2 R32.2 R35.2 R37.2 R42.2 R43.2 R44.2 R45.2 R58.2 R60.2 R64.2 R66.2 R91.1 R102.2 R107.2 R108.2 R111.1 R113.2 R120.2 R121.2 R122.2 R123.2 R129.2 R130.1 R134.2 R135.2 R140.2 R141.2 R154.2 R155.2 R156.2 R157.2 R161.2 R164.2 R167.2 R168.2 R169.2 R170.2 SW1.5 SW2.5 TP3.1 U7.40 U8.5 U9.5 U9.11 U9.15 U9.38 U9.67 U9.76 U15.5 U18.5 U19.1 U19.10 U20.12 U21.5 U23.5 U25.5 U27.5 U28.5 U29.7 U29.8 U29.9 U29.16 U29.26 U29.28 U29.39 U29.47 U29.51 U29.52 U29.69 U29.79 U29.90 U29.101 U29.113 U29.122 U33.1 U34.1 | length 4901.2
  Top Layer w5.91: L4.2@879.92,1712.6 L4.2@880.91,1711.61
  Top Layer w7.87: v1(954.73,4537.4) C154.2@984.25,4537.4 988.18,4541.34 U29.101@1055.12,4541.34 ; v1(961.59,4202.75) C155.2@984.26,4202.75 992.13,4210.63 U29.122@1055.12,4210.63 ; v1(1010.91,4365.53) 1010.91,4363.11 1021.65,4352.36 U29.113@1055.12,4352.36 ; U29.7@1208.66,4057.09 U29.8@1224.41,4057.09 ; v1(1208.66,4615.68) U29.90@1208.66,4663.39 ; v1(1216.54,3893.7) C157.1@1216.54,3927.17 1224.41,3935.04 U29.8@1224.41,4057.09 ; U29.9@1240.16,4057.09 U29.8@1224.41,4057.09 ; v1(1338.58,4005.91) 1338.58,4005.98 1350.39,4017.79 U29.16@1350.39,4057.09 ; U29.79@1381.89,4663.39 1381.89,4688.98 1396.16,4703.25 1421.75,4703.25 1433.07,4714.57 C156.1@1433.07,4734.25 1429.13,4734.25 1417.27,4746.12 1417.27,4746.31 1412.65,4750.92 1400.65,4750.92 v1(1397.64,4753.94) ; v1(1397.64,4832.68) R161.2@1433.07,4832.68 ; U29.26@1507.87,4057.09 1507.87,4016.73 1515.75,4008.86 C151.2@1515.75,3986.22 ; v1(1515.75,3956.69) C151.2@1515.75,3986.22 ; U29.28@1539.37,4057.09 1539.37,3990.84 1534.76,3986.22 C151.2@1515.75,3986.22 ; U29.69@1539.37,4663.39 v1(1539.37,4710.63) ; v1(1539.37,5082.68) 1543.31,5082.68 1566.93,5059.06 R169.2@1570.87,5059.06 R170.2@1570.87,5009.84 ; R164.2@1618.11,4783.46 v1(1653.54,4783.46) ; U29.39@1661.42,4210.63 1720.47,4210.63 C152.2@1732.28,4222.44 v1(1761.81,4222.44) ; U29.47@1661.42,4336.61 1706.69,4336.61 v1(1712.6,4330.71) ; U29.52@1661.42,4415.35 U29.51@1661.42,4399.61 C153.2@1732.28,4399.61 v1(1761.81,4399.61) ; v1(1696.85,4659.45) R154.2@1732.28,4659.45 R155.2@1781.5,4659.45 R156.2@1830.71,4659.45 ; v1(1781.5,4438.98) R157.2@1781.5,4474.41 ; U34.1@1804.86,5053.82 1805.5,5054.47 1830.06,5054.47 v1(1830.71,5055.12) ; v1(3159.45,2824.8) 3162.09,2827.44 3162.09,2831.38 3181.1,2850.39 R107.2@3185.04,2850.39 ; v1(3228.35,3094.49) 3271.65,3094.49 3299.21,3066.93 R102.2@3303.15,3066.93 ; C120.1@3350.39,3017.72 3352.36,3019.69 v1(3381.89,3019.69) 3405.51,3019.69 3411.42,3025.59 U15.5@3420.28,3025.59 ; v1(4129.92,2901.57) R91.1@4161.42,2901.57 ; v1(4283.39,2877.95) 4283.46,2877.95 Q12.2@4283.46,2901.57
  Top Layer w9.84: v1(1333.66,3237.2) U8.5@1333.66,3265.75 ; v1(1578.74,2972.44) R35.2@1610.24,2972.44 ; v1(1596.46,2824.8) R31.2@1634.79,2824.8 ; v1(1598.43,2767.72) 1600.39,2765.75 R32.2@1634.79,2765.75 ; R37.2@1614.17,3301.18 v1(1614.17,3334.65) ; R43.2@2072.83,4419.29 v1(2072.83,4452.9) ; v1(2145.67,4242.13) 2146.72,4243.17 2195.93,4243.17 2224.41,4271.65 2260.33,4271.65 2270.18,4281.5 U9.15@2314.96,4281.5 ; v1(2145.67,4301.18) 2146.72,4300.13 2203.68,4300.13 2224.41,4320.87 C80.1@2228.35,4320.87 2233.86,4326.38 2251.58,4326.38 2284.45,4359.25 2313.98,4359.25 U9.11@2314.96,4360.24 ; v1(2145.67,4488.19) 2146.72,4489.24 2203.68,4489.24 2224.41,4468.5 C79.1@2228.35,4468.5 2260.33,4468.5 2270.18,4478.35 U9.5@2314.96,4478.35 ; v1(2259.84,976.38) R168.2@2283.46,976.38 ; R167.2@2339.65,976.92 2341.04,978.31 2341.04,1010.81 v1(2342.42,1012.19) ; C84.1@2450.79,4720.47 2451.45,4719.81 2451.45,4695.73 v1@2466.04,4681.13 ; R42.2@2450.79,4875.98 2450.86,4876.06 2450.86,4911.35 v1(2450.93,4911.42) ; v1@2463.09,4677.66 2469.49,4671.26 2469.49,4634.84 U9.76@2470.47,4633.86 ; v1(2492.13,1413.39) C139.1@2519.68,1413.39 2563.98,1413.39 2579.72,1397.64 U23.5@2579.72,1385.83 ; v1(2519.68,1663.39) 2539.37,1643.7 R141.2@2539.37,1618.11 ; R44.2@2549.21,4875.98 v1(2549.21,4911.42) ; FB1.2@2586.61,3830.71 v1(2629.92,3830.71) ; U33.1@2647.24,1663.39 2648.23,1662.4 2695.87,1662.4 v1(2696.85,1661.42) R140.2@2696.85,1618.11 ; U9.67@2647.64,4633.86 C83.1@2647.64,4720.47 2647.64,4724.41 2671.34,4748.11 v1(2671.34,4801.1) ; R45.2@2647.64,4875.98 v1(2647.64,4911.42) ; L9.1@2708.66,2814.96 2708.83,2815.13 v1(2747.41,2815.13) ; U9.38@2726.38,4106.3 2727.36,4105.32 2727.36,4065.21 2735.41,4057.17 2735.41,4022.72 2749.82,4008.31 2757.9,4008.31 v1(2760.53,4005.67) ; v1(2868.11,1423.23) C134.1@2893.7,1423.23 2937.99,1423.23 2953.74,1407.48 U21.5@2953.74,1395.67 ; R135.2@2913.39,1627.95 v1(2913.39,1661.42) ; v1(2992.13,4074.8) R58.2@2992.13,4106.3 ; R134.2@3070.87,1627.95 v1(3070.87,1673.23) ; U19.10@3435.04,830.71 3490.16,830.71 3503.94,816.93 C127.1@3503.94,812.99 v1(3503.94,775.59) ; U19.1@3435.04,940.94 3490.16,940.94 3509.84,960.63 v1(3535.43,960.63) ; R121.2@3437.01,2244.09 v1(3466.54,2244.09) ; R122.2@3437.01,2458.66 3466.54,2458.66 v1(3468.5,2460.63) ; v1(3456.69,4391.73) R60.2@3494.09,4391.73 ; R123.2@3503.94,1057.09 3505.91,1055.12 v1(3535.43,1055.12) ; v1(3636.6,1601.5) 3636.72,1601.38 3654.53,1601.38 3661.42,1594.49 C149.1@3661.42,1590.55 ; C149.1@3662.22,1585.81 3666.34,1581.69 3710.63,1581.69 U28.5@3715.55,1576.77 ; v1(3740.16,3649.61) SW2.5@3777.56,3649.61 ; v1(3742.13,935.04) R130.1@3775.59,935.04 ; v1(3779.53,4354.33) 3779.53,4337.6 3782.48,4334.65 R64.2@3783.46,4334.65 ; R129.2@3844.49,803.15 3840.55,803.15 3822.83,820.87 C129.1@3822.83,875.98 U20.12@3872.05,875.98 ; R113.2@3858.27,2289.37 v1(3883.86,2289.37) ; R120.2@3966.73,2075.57 v1(3966.73,2111) 3969.37,2113.64 3992.78,2113.64 4003.93,2124.78 Q15.2@4021.85,2124.78 ; v1(3969.49,4200.79) SW1.5@4005.91,4200.79 ; U18.5@3971.46,2366.14 3980.31,2366.14 3992.13,2354.33 C124.2@3992.13,2312.99 v1(3992.13,2287.4) ; R108.2@4082.68,2137.8 v1(4110.24,2137.8) ; v1(4133.86,1433.07) C148.1@4163.39,1433.07 ; v1(4133.86,1578.74) 4135.83,1580.71 C147.1@4163.39,1580.71 4163.39,1578.4 4170.28,1571.51 4212.94,1571.51 U25.5@4217.52,1566.93 ; C148.1@4163.21,1428.09 4167.62,1423.69 4213.12,1423.69 U27.5@4217.52,1419.29 ; R111.1@4281.5,2139.76 v1(4281.5,2175.2) ; v1(4345.56,4199.15) 4345.56,4231.38 R66.2@4346.46,4232.28
  Bottom Layer w7.87: v1@1009.43,4367.01 v1(1010.91,4365.53)
  other v1: 3822.83,846.46 1181.1,1633.86 1151.57,1663.39 1210.63,1663.39 1181.1,1692.91 1151.57,1722.44 1210.63,1722.44 2338.58,3188.98 3169.29,4342.52 3169.29,4374.02 2466.04,4680.61
3V3_FB: C16.2 C17.2 L4.1 L5.2 R15.2 R16.2 | length 561.8
  Top Layer w5.91: R15.2@881.89,1082.68 885.83,1082.68 894.68,1091.54 894.68,1092.48 904.59,1102.38 904.59,1148.1 890.48,1162.21 890.06,1162.21 885.51,1166.76 R16.2@885.51,1171.26 ; R16.2@885.51,1173.23 854.33,1173.23 807.09,1220.47 807.09,1427.17 828.08,1448.16 863.22,1448.16 879.44,1464.38 879.44,1493.11 894.21,1507.87 C17.2@905.51,1507.87
5V: C11.2 C12.2 C135.1 C140.1 J2.2 J26.5 L2.2 L7.1 R9.2 R10.2 R145.1 R149.1 TP1.1 U21.3 U23.3 | length 982.2
  Top Layer w5.91: C11.2@879.47,2460.63 839.97,2460.63 810.85,2431.51 810.85,2183.24 887.8,2106.3 R10.2@891.73,2106.3 895.67,2106.3 914.43,2087.54 914.43,2026.64 895.67,2007.87 R9.2@891.73,2007.87
  Top Layer w9.84: TP1.1@807.09,2578.74 J2.2@924.41,2578.74 ; v1(2594.49,1590.55) C140.1@2594.49,1564.96 2598.43,1564.96 2605.31,1558.07 U23.3@2605.31,1488.19 ; v1(2972.88,1602.24) 2972.88,1579.18 C135.1@2968.5,1574.8 2972.44,1574.8 2979.33,1567.91 U21.3@2979.33,1498.03 ; R149.1@4478.35,1433.07 4478.35,1429.13 4500.91,1406.57 v1(4502.82,1406.57) ; R145.1@4478.35,1627.95 4478.35,1631.89 4498.03,1651.57 v1(4500.9,1651.57)
  Bottom Layer w9.84: v1(4500.9,1651.57) v1@4502.86,1653.54 ; v1(4502.82,1406.57) v1@4506.97,1406.57
  other v1: 1505.91,2155.51 1604.33,2155.51 1476.38,2185.04 1505.91,2214.57 1604.33,2214.57 874.02,2515.75 923.23,2515.75 972.44,2515.75
12V: C1.1 C2.2 C3.2 C118.1 C119.2 F1.2 J14.2 J30.1 L1.1 L3.1 R3.1 R97.1 R104.1 R148.2 U1.6 U14.7 U14.8 | length 382.6
  Top Layer w9.84: R104.1@3208.66,2921.26 3226.38,2903.54 v1(3494.09,2903.54) ; R97.1@3897.64,3147.64 v1(3897.64,3194.17) ; v1(4523.62,1137.8) R148.2@4523.62,1181.1
  other v1: 1007.87,854.33 1066.93,854.33 1125.98,854.33 1037.4,883.86 1096.46,883.86 1007.87,913.39 1066.93,913.39 1125.98,913.39 1037.4,942.91 1096.46,942.91 4232.28,1889.76 4311.02,1889.76 1033.46,1899.61 1082.68,1899.61 1131.89,1899.61 4271.65,1909.45 4232.28,1929.13 4311.02,1929.13 1112.2,1938.98 1112.2,1988.19 4236.22,3082.68 4206.69,3112.2 4236.22,3141.73 4206.69,3171.26 4236.22,3200.79 3425.2,5059.06 3484.25,5059.06 3543.31,5059.06 3602.36,5059.06 3395.67,5088.58 3454.72,5088.58 3513.78,5088.58 3572.83,5088.58
+12V_EXT: J26.1 J26.2 R3.2
+12Va: C24.2 C25.2 C26.1 C90.2 C114.2 C115.2 C116.1 D9.2 R20.2 R70.1 R82.1 TP6.1 U6.10 U10.6 U11.1 U11.5 U12.5 U13.5 | length 7659
  Top Layer w7.87: R82.1@3996.06,3771.65 v1(4023.62,3771.65)
  Top Layer w9.84: v1(3663.39,4127.95) 3663.39,4217.52 U10.6@3669.29,4223.43 ; v1(3937.01,4429.13) R70.1@3976.38,4429.13 ; v1(4106.3,3515.75) U11.1@4106.3,3548.23 ; U11.5@4106.3,3656.5 4109.24,3659.43 4109.24,3721.44 C114.2@4114.17,3726.38 4114.17,3729.33 4121.06,3736.22 v1(4141.73,3736.22) ; v1(4234.42,3736.22) 4254.92,3736.22 4261.81,3729.33 C115.2@4261.81,3726.38 4263.78,3724.41 U12.5@4263.78,3656.5 ; v1(4340.55,3736.22) 4363.19,3736.22 4370.08,3729.33 C116.1@4370.08,3726.38 4371.37,3725.09 4371.37,3703.43 4404.64,3670.17 4413.39,3670.17 4421.26,3662.29 U13.5@4421.26,3653.54
  Top Layer w23.62: R82.1@3996.06,3771.65 R82.1@3996.06,3773.62
  Inner Layer 2 w23.62: v1(2057.72,708.75) 2070.53,695.94 4190.03,695.94 4433.07,938.98 4433.07,1763.78 4492.13,1822.83 4492.13,2492.13 4423.23,2561.02 4423.23,2561.33 4397.57,2586.98 4397.57,2893.33 4436.94,2932.7 4436.94,3307.15 4381.17,3362.92 4381.17,3796.42 4527.5,3942.74 4527.5,4200.85 4299.21,4429.13 v1(3937.01,4429.13) 3751.97,4429.13 3663.39,4340.55 v1(3663.39,4127.95)
  other v1: 2017.72,708.66 2037.14,746.46
+14V_EXT: C22.1 D8.1 D9.1 J26.3 TP5.1 U6.1 U6.2 | length 4933.8
  Bottom Layer w23.62: v1(1905.51,1377.95) 1905.51,1429.13 2001.97,1525.59 2706.69,1525.59 3256.97,2075.87 3256.97,4619.59 3170.56,4706 3170.56,5053.65 3106.1,5118.11 3106.1,5205.71 J26.3@3055.91,5255.91
  other v1: 1925.2,1287.4 1877.95,1334.65 1925.2,1334.65
-12Va: C36.2 C37.2 C39.1 C92.2 D12.1 R28.2 TP8.1 U6.6 U10.2 U10.5 | length 7755.5
  Top Layer w9.84: v1(3600.39,4427.17) 3600.39,4388.97 C92.2@3601.38,4388.97 ; C92.2@3608.27,4388.97 3612.2,4388.97 3631.89,4369.28 U10.2@3631.89,4331.69 U10.5@3631.89,4223.43
  Inner Layer 2 w23.62: v1(1549.89,661.33) 1556.87,668.31 4201.47,668.31 4460.69,927.53 4460.69,1752.34 4519.75,1811.39 4519.75,2503.57 4515.75,2507.57 4515.75,2507.87 4425.2,2598.43 4425.2,2881.89 4464.57,2921.26 4464.57,3318.59 4408.8,3374.36 4408.8,3784.98 4555.12,3931.3 4555.12,4212.6 4314.96,4452.76 4314.65,4452.76 4309.65,4457.76 3741.53,4457.76 3736.53,4452.76 3736.22,4452.76 3710.63,4427.17 v1(3600.39,4427.17)
  other v1: 1589.89,661.42 1569.31,699.13
-14V_EXT: C31.1 D10.2 D12.2 J26.4 TP7.1 U6.5 | length 4901.7
  Bottom Layer w23.62: v1(1724.41,1377.95) 1724.41,1417.32 1931.1,1624.02 2706.69,1624.02 3198.27,2115.6 3198.27,4511.48 3055.91,4653.85 J26.4@3055.91,5155.91
  other v1: 1700.79,1287.4 1700.79,1334.65 1748.03,1334.65
AM62L_GPIO_EV_PlugIN: J28.2 SW1.7 | length 5952.9
  Top Layer w5.91: v1(2086.61,3484.25) 2726.38,3484.25 3238.19,3996.06 v1(3474.41,3996.06) ; v1(3750,3986.22) 4064.96,3986.22 4156.46,4077.72 4156.46,4142.68 4202.76,4188.98 SW1.7@4202.76,4200.79
  Bottom Layer w5.91: J28.2@421.85,3820.47 344.49,3897.83 344.49,4626.91 386.87,4669.29 586.61,4669.29 1053.15,4202.76 1053.15,3523.62 1092.52,3484.25 v1(2086.61,3484.25) ; v1(3474.41,3996.06) 3484.25,3986.22 v1(3750,3986.22)
AM62L_GPIO_GBT_EV_PlugIN: J28.4 SW2.7 | length 4475
  Top Layer w5.91: J28.4@421.85,3920.47 472.24,3870.08 637.8,3870.08 688.98,3818.9 688.98,3523.62 1102.36,3110.24 1653.54,3110.24 1692.91,3149.61 v1(1692.91,3326.77) ; v1(2125.98,3444.88) v1(2618.11,3444.88) ; v1(3011.81,3503.94) 3165.35,3503.94 3194.88,3474.41 3887.61,3474.41 3907.48,3494.28 3907.48,3600.39 3949.33,3642.24 3967.04,3642.24 SW2.7@3974.41,3649.61
  Bottom Layer w5.91: v1(1692.91,3326.77) 2007.87,3326.77 v1(2125.98,3444.88) ; v1(2618.11,3444.88) 2677.17,3503.94 v1(3011.81,3503.94)
AM62L_I2C3_SCL: J28.24 J32.1 R169.1 U34.3 | length 1777.8
  Top Layer w5.91: J28.24@421.85,4920.47 374.02,4968.31 374.02,5049.21 393.7,5068.9 600.39,5068.9 732.44,5200.95 1495.9,5200.95 1618.11,5078.74 R169.1@1618.11,5059.06 1623.34,5053.82 U34.3@1765.49,5053.82 1765.49,5154.9 J32.1@1764.48,5155.91
AM62L_I2C3_SDA: J28.26 J32.2 R170.1 U34.5 | length 1832.8
  Top Layer w5.91: J28.26@421.85,5020.47 462.01,4980.31 580.71,4980.31 771.55,5171.15 1403.65,5171.15 1466.54,5108.27 1466.54,5045.28 1531.5,4980.31 1584.65,4980.31 1614.17,5009.84 R170.1@1618.11,5009.84 1692.91,5009.84 1727.34,4975.42 1773.13,4975.42 1793.27,4995.56 U34.5@1804.86,4995.56 1836.11,4995.56 1864.48,5023.93 J32.2@1864.48,5155.91
AM62L_MSP_BSL: J28.14 R38.2 U8.2 | length 1746.5
  Top Layer w5.91: J28.14@421.85,4420.47 472.24,4370.08 472.24,4200.98 500,4173.23 602.36,4173.23 629.92,4145.67 629.92,4035.43 767.72,3897.64 767.72,3523.62 1058.98,3232.36 1137.72,3232.36 1165.35,3204.72 R38.2@1165.35,3179.13 ; R38.2@1165.86,3178.63 1186.5,3178.63 1196.51,3188.64 1196.51,3207.34 1217.52,3228.35 U8.2@1225.39,3228.35
AM62L_MSP_R\S\T\: J28.10 Q4.1@1555.12,3159.45 R40.1 | length 1907.9
  Top Layer w5.91: J28.10@421.85,4220.47 472.44,4169.88 472.44,4094.49 500,4066.93 539.37,4066.93 728.35,3877.95 728.35,3523.62 1112.2,3139.76 1535.43,3139.76 Q4.1@1555.12,3159.45 1604.33,3159.45 1614.17,3149.61 R40.1@1614.17,3145.67
AM62L_RS232_RX: J28.13 R131.2 TP48.1 | length 5854.9
  Top Layer w5.91: J28.13@521.85,4420.47 480.44,4461.89 377.24,4461.89 334.65,4419.29 334.65,3671.26 383.86,3622.05 531.5,3622.05 570.87,3582.68 570.87,3523.62 1631.68,2462.81 1926.96,2462.81 2135.83,2253.94 2746.06,2253.94 3784.94,1215.07 TP48.1@3809.06,1215.07 3846.95,1177.17 3984.25,1177.17 4015.75,1145.67 4015.75,1098.43 3975.44,1058.12 R131.2@3956.69,1058.12
AM62L_RS232_TX: J27.8 R128.2 TP46.1 | length 4555.6
  Top Layer w5.91: J27.8@421.85,3570.47 472.32,3520.01 535.11,3520.01 1633.95,2421.16 1929.23,2421.16 2125.98,2224.41 2736.22,2224.41 3809.06,1151.57 TP46.1@3809.06,1125.98 3809.06,1084.65 3835.58,1058.12 R128.2@3897.64,1058.12
AM62L_RS485_DIR: J28.23 R127.2 U19.3 U19.4 | length 6393.7
  Top Layer w5.91: J28.23@521.85,4920.47 590.55,4851.77 590.55,4507.87 564.36,4481.68 351.28,4481.68 295.28,4425.67 295.28,3464.57 344.49,3415.35 600.39,3415.35 1636.27,2379.48 1931.54,2379.48 2116.14,2194.88 2726.38,2194.88 3405.51,1515.75 3405.51,1417.32 3523.62,1299.21 3523.62,1161.42 v1(3484.25,1122.05) ; U19.4@3375.98,940.94 U19.3@3395.67,940.94 3393.9,942.72 3393.9,960.8 3386.03,968.67 v1(3386.03,973.46) 3386.03,993.59 3386.81,994.37 3386.81,1000.98 R127.2@3395.67,1009.84
  Bottom Layer w5.91: v1(3386.03,973.46) 3484.25,1071.68 v1(3484.25,1122.05)
AM62L_RS485_RX: J28.20 R126.2 TP43.1 | length 5913.2
  Top Layer w5.91: J28.20@421.85,4720.47 474.56,4667.76 474.56,4584.57 449.77,4559.78 327.5,4559.78 255.91,4488.19 255.91,3425.2 360.73,3320.37 656,3320.37 1637.57,2338.81 1932.84,2338.81 2106.3,2165.35 2716.54,2165.35 3366.14,1515.75 3366.14,1397.64 TP43.1@3444.88,1318.9 3484.25,1279.53 3484.25,1181.1 3444.88,1141.73 R126.2@3444.88,1048.28
AM62L_RS485_TX: J28.18 R125.2 TP42.1 | length 5827.7
  Top Layer w5.91: J28.18@421.85,4620.47 289.76,4620.47 216.54,4547.24 216.54,3405.23 413.1,3208.66 728.35,3208.66 1641.73,2295.28 1937.01,2295.28 2096.46,2135.83 2706.69,2135.83 3326.77,1515.75 3326.77,1358.27 TP42.1@3444.88,1240.16 3444.88,1200.79 3346.46,1102.36 R125.2@3346.46,1048.28
AM62L_UART_RX: J27.10 R31.1 R33.2 | length 1800.8
  Top Layer w5.91: J27.10@421.85,3670.47 481.69,3730.31 580.71,3730.31 649.61,3661.42 649.61,3523.62 1318.9,2854.33 1648.57,2854.33 1678.1,2824.8 R31.1@1682.04,2824.8 R33.2@1742.03,2824.8
AM62L_UART_TX: J27.9 R32.1 R34.2 | length 1688.6
  Top Layer w5.91: J27.9@521.85,3670.47 581.5,3670.47 610.24,3641.73 610.24,3523.62 1397.64,2736.22 1652.51,2736.22 R32.1@1682.04,2765.75 R34.2@1742.03,2765.75
ANALOG_IN_1: D35.1 J22.2 R152.2 | length 1728.7
  Top Layer w5.91: R152.2@3931.1,1633.86 3984.25,1633.86 3996.06,1622.05 D35.1@3996.06,1562.99 3999.49,1559.56 4109.73,1559.56 4133.86,1535.43 4232.28,1535.43 4271.65,1496.06 4271.65,1299.21 4291.34,1279.53 4763.78,1279.53 5117.62,1633.37 J22.2@5216.54,1633.37
BSL: U7.11 U8.4 | length 1335.4
  Top Layer w5.91: U8.4@1333.66,3190.94 1335.63,3188.98 v1(1456.69,3188.98) ; v1(1791.34,2598.43) 1909.45,2598.43 1998.03,2687.01 2116.14,2687.01 2175.2,2627.95 U7.11@2175.2,2590.55
  Bottom Layer w5.91: v1(1456.69,3188.98) 1791.34,2854.33 v1(1791.34,2598.43)
CAN1_N: C138.2 J18.2 L21.3 R137.1 R138.2 U22.1 | length 1323.5
  Top Layer w9.84: R138.2@2883.86,1163.39 2895.67,1151.57 2930.12,1151.57 2942.91,1138.78 L21.3@2942.91,1130.91 R137.1@2942.91,1051.18 2942.91,1013.78 2889.76,960.63 2889.76,850.39 2922.1,818.05 2937.85,818.05 C138.2@2942.91,812.99 2942.91,767.72 2954.72,755.91 U22.1@2954.72,706.69 2979.44,706.69 2985.2,700.93 2985.2,547.41 3249.38,283.24 3249.38,143.56 3243.61,137.8 J18.2@3187.4,137.8
CAN1_P: C136.1 J18.3 L21.4 R133.2 R136.2 U22.2 | length 1323.5
  Top Layer w9.84: R133.2@3100.39,1163.39 3088.58,1151.57 3054.13,1151.57 3041.34,1138.78 L21.4@3041.34,1130.91 R136.2@3041.34,1051.18 3041.34,1013.78 3094.49,960.63 3094.49,850.39 3062.15,818.05 3046.4,818.05 C136.1@3041.34,812.99 3041.34,767.72 3029.53,755.91 U22.2@3029.53,706.69 3004.81,706.69 2999.05,700.93 2999.05,553.14 3263.22,288.97 3263.22,143.56 3268.99,137.8 J18.3@3325.2,137.8
CAN1_RX: J28.15 R135.1 U21.4 | length 4726.7
  Top Layer w5.91: v1(2724.41,1787.4) 2874.02,1637.8 2874.02,1602.36 2895.67,1580.71 R135.1@2913.39,1580.71 ; R135.1@2913.39,1584.65 R135.1@2913.39,1580.71 ; U21.4@2953.74,1498.03 2953.74,1524.61 2942.91,1535.43 2923.23,1535.43 2913.39,1545.28 R135.1@2913.39,1580.71
  Bottom Layer w5.91: J28.15@521.85,4520.47 893.7,4148.62 893.7,3220.47 1433.07,2681.1 1433.07,1933.07 1578.74,1787.4 v1(2724.41,1787.4)
CAN1_TX: J28.7 R134.1 U21.1 | length 4629.1
  Top Layer w5.91: v1(2787.4,1787.4) 2868.11,1787.4 3070.87,1584.65 R134.1@3070.87,1580.71 3070.87,1545.28 3061.02,1535.43 3041.34,1535.43 3030.51,1524.61 U21.1@3030.51,1498.03
  Bottom Layer w5.91: J28.7@521.85,4120.47 682.68,4120.47 830.71,3972.44 830.71,3204.72 1385.83,2649.61 1385.83,1913.39 1552.72,1746.49 2746.49,1746.49 v1(2787.4,1787.4)
CAN2_N: C143.2 J19.2 L22.3 R143.1 R144.2 U24.1 | length 1306.5
  Top Layer w9.84: R144.2@2507.87,1155.51 2520.67,1142.72 2556.1,1142.72 2568.9,1129.92 L22.3@2568.9,1121.06 R143.1@2568.9,1043.31 2568.9,1005.79 2515.75,952.64 2515.75,830.71 2543.31,803.15 C143.2@2568.9,803.15 2568.9,764.27 2580.71,752.46 U24.1@2580.71,696.85 2605.42,696.85 2611.19,691.08 2611.19,522.8 2835.99,298 2835.99,143.56 2830.23,137.8 J19.2@2774.02,137.8
  other v1: 2587.14,744.66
